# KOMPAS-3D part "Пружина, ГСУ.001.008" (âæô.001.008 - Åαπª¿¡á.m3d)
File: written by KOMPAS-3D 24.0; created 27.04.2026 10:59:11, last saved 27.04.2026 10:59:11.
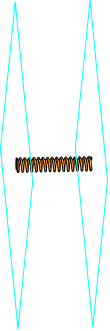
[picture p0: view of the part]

Document properties: Автор: User7; Полное имя файла: C:\Users\User7\Desktop\Двигатель мясорубки\ГСУ.001.008 - Пружина.m3d

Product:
- Part/product: Пружина  | designation ГСУ.001.008
    Масса: 0.000147

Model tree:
1. Спираль рабочих витков
     Шаг = 0.9875; Диаметр 2 = 10
2. Сечение проволоки  (labels: Смещенная плоскость 1)
     Толщина стенки 1 = 0.01; Толщина стенки 2 = 0.01; Длина траектории = 141.627; Шаг = 0.4; Диаметр 2 = 10; Шаг = 0.4; Направление навивки = 139296; Диаметр 2 = 10; Толщина стенки 1 = 0.01; Толщина стенки 2 = 0.01; Длина траектории = 6.60416
3. Сечение проволоки 2
     Толщина стенки 1 = 0.01; Толщина стенки 2 = 0.01; Длина траектории = 6.60416
4. Секущая плоскость 1  (labels: Сечение плоскостью 1)
5. Секущая плоскость 2  (labels: Сечение плоскостью 2)
6. Плоскость для сопряжений 1
7. Плоскость для сопряжений 2
8. Пружина

Expressions: L-(d+2*n2*d-2*n3*d); 0.5*d+(n2*d-n3*d); L-(d+2*n2*d-2*n3*d)+0.5*d+(n2*d-n3*d); (D1-d)/2
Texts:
  ГСУ.001.008
  Расстояние от центра до окружности
  Направление навивки (1 - правое; 0 - левое)
  Наружный диаметр пружины, мм
  Диаметр проволоки, мм
  Число рабочих витков
  Число поджатых витков с одной стороны
  Число обработанных витков с одной стороны
  Кинематическая операция для рабочих витков
  Спираль первого поджатого витка
  Спираль второго поджатого витка
  Кинематическая операция для первого поджатого витка
  Кинематическая операция для второго поджатого витка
